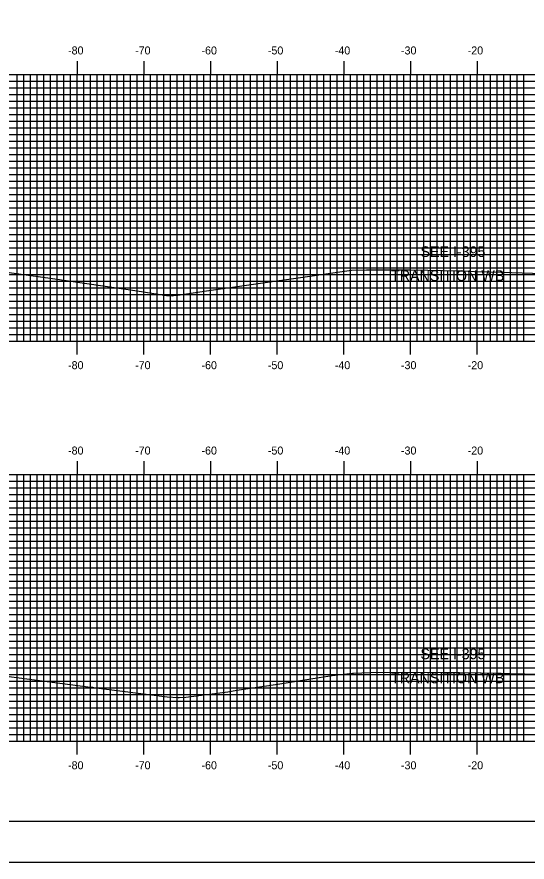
# Model space of a CAD drawing. Extents: x 854508 to 854851, y 364661 to 364881.
# Drawn here: x 854584.8 to 854661.3, y 364661.3 to 364788 of the extents above; entities that cross this region are included whole.
import ezdxf

# ---------------------------------------------------------------- set-up
doc = ezdxf.new("R2010")
doc.units = 0
for name, color, linetype in [('ANNOTATION', 7, 'Continuous'), ('BORDER', 7, 'Continuous'), ('H_V ANNOTATION', 7, 'Continuous'), ('M_Roadway_Centerline', 7, 'Continuous'), ('MAJOR', 7, 'Continuous'), ('MINOR', 7, 'Continuous'), ('PLOT BOUNDARY', 7, 'Continuous'), ('S_Roadway_Centerline', 7, 'Continuous')]:
    doc.layers.add(name, color=color, linetype=linetype)

msp = doc.modelspace()

# ---------------------------------------------------------------- linework, layer by layer
at = {"layer": 'BORDER'}
msp.add_lwpolyline([(854524.23, 364667.37), (854844.23, 364667.37), (854844.23, 364877.37), (854524.23, 364877.37)], close=True, dxfattribs=at)
at = {"layer": 'MAJOR'}
for p, q in [((854593.83, 364781.37), (854593.83, 364779.37)), ((854603.83, 364781.37), (854603.83, 364779.37)), ((854613.83, 364781.37), (854613.83, 364779.37)), ((854623.83, 364781.37), (854623.83, 364779.37)), ((854633.83, 364781.37), (854633.83, 364779.37)), ((854643.83, 364781.37), (854643.83, 364779.37)), ((854653.83, 364781.37), (854653.83, 364779.37)), ((854533.83, 364779.37), (854813.83, 364779.37)), ((854533.83, 364779.37), (854813.83, 364779.37)), ((854593.83, 364739.37), (854593.83, 364779.37)), ((854603.83, 364739.37), (854603.83, 364779.37)), ((854613.83, 364739.37), (854613.83, 364779.37)), ((854623.83, 364739.37), (854623.83, 364779.37)), ((854633.83, 364739.37), (854633.83, 364779.37)), ((854643.83, 364739.37), (854643.83, 364779.37)), ((854653.83, 364739.37), (854653.83, 364779.37)), ((854533.83, 364774.37), (854813.83, 364774.37)), ((854533.83, 364769.37), (854813.83, 364769.37)), ((854533.83, 364764.37), (854813.83, 364764.37)), ((854533.83, 364759.37), (854813.83, 364759.37)), ((854533.83, 364754.37), (854813.83, 364754.37)), ((854533.83, 364749.37), (854813.83, 364749.37)), ((854533.83, 364744.37), (854813.83, 364744.37)), ((854533.83, 364739.37), (854813.83, 364739.37)), ((854533.83, 364739.37), (854813.83, 364739.37)), ((854593.83, 364737.37), (854593.83, 364739.37)), ((854603.83, 364737.37), (854603.83, 364739.37)), ((854613.83, 364737.37), (854613.83, 364739.37)), ((854623.83, 364737.37), (854623.83, 364739.37)), ((854633.83, 364737.37), (854633.83, 364739.37)), ((854643.83, 364737.37), (854643.83, 364739.37)), ((854653.83, 364737.37), (854653.83, 364739.37)), ((854593.83, 364721.37), (854593.83, 364719.37)), ((854603.83, 364721.37), (854603.83, 364719.37)), ((854613.83, 364721.37), (854613.83, 364719.37)), ((854623.83, 364721.37), (854623.83, 364719.37)), ((854633.83, 364721.37), (854633.83, 364719.37)), ((854643.83, 364721.37), (854643.83, 364719.37)), ((854653.83, 364721.37), (854653.83, 364719.37)), ((854533.83, 364719.37), (854813.83, 364719.37)), ((854533.83, 364719.37), (854813.83, 364719.37)), ((854593.83, 364679.37), (854593.83, 364719.37)), ((854603.83, 364679.37), (854603.83, 364719.37)), ((854613.83, 364679.37), (854613.83, 364719.37)), ((854623.83, 364679.37), (854623.83, 364719.37)), ((854633.83, 364679.37), (854633.83, 364719.37)), ((854643.83, 364679.37), (854643.83, 364719.37)), ((854653.83, 364679.37), (854653.83, 364719.37)), ((854533.83, 364714.37), (854813.83, 364714.37)), ((854533.83, 364709.37), (854813.83, 364709.37)), ((854533.83, 364704.37), (854813.83, 364704.37)), ((854533.83, 364699.37), (854813.83, 364699.37)), ((854533.83, 364694.37), (854813.83, 364694.37)), ((854533.83, 364689.37), (854813.83, 364689.37)), ((854533.83, 364684.37), (854813.83, 364684.37)), ((854533.83, 364679.37), (854813.83, 364679.37)), ((854533.83, 364679.37), (854813.83, 364679.37)), ((854593.83, 364677.37), (854593.83, 364679.37)), ((854603.83, 364677.37), (854603.83, 364679.37)), ((854613.83, 364677.37), (854613.83, 364679.37)), ((854623.83, 364677.37), (854623.83, 364679.37)), ((854633.83, 364677.37), (854633.83, 364679.37)), ((854643.83, 364677.37), (854643.83, 364679.37)), ((854653.83, 364677.37), (854653.83, 364679.37))]:
    msp.add_line(p, q, dxfattribs=at)
at = {"layer": 'MINOR'}
for p, q in [((854533.83, 364778.37), (854813.83, 364778.37)), ((854584.83, 364739.37), (854584.83, 364779.37)), ((854585.83, 364739.37), (854585.83, 364779.37)), ((854586.83, 364739.37), (854586.83, 364779.37)), ((854587.83, 364739.37), (854587.83, 364779.37)), ((854588.83, 364739.37), (854588.83, 364779.37)), ((854589.83, 364739.37), (854589.83, 364779.37)), ((854590.83, 364739.37), (854590.83, 364779.37)), ((854591.83, 364739.37), (854591.83, 364779.37)), ((854592.83, 364739.37), (854592.83, 364779.37)), ((854594.83, 364739.37), (854594.83, 364779.37)), ((854595.83, 364739.37), (854595.83, 364779.37)), ((854596.83, 364739.37), (854596.83, 364779.37)), ((854597.83, 364739.37), (854597.83, 364779.37)), ((854598.83, 364739.37), (854598.83, 364779.37)), ((854599.83, 364739.37), (854599.83, 364779.37)), ((854600.83, 364739.37), (854600.83, 364779.37)), ((854601.83, 364739.37), (854601.83, 364779.37)), ((854602.83, 364739.37), (854602.83, 364779.37)), ((854604.83, 364739.37), (854604.83, 364779.37)), ((854605.83, 364739.37), (854605.83, 364779.37)), ((854606.83, 364739.37), (854606.83, 364779.37)), ((854607.83, 364739.37), (854607.83, 364779.37)), ((854608.83, 364739.37), (854608.83, 364779.37)), ((854609.83, 364739.37), (854609.83, 364779.37)), ((854610.83, 364739.37), (854610.83, 364779.37)), ((854611.83, 364739.37), (854611.83, 364779.37)), ((854612.83, 364739.37), (854612.83, 364779.37)), ((854614.83, 364739.37), (854614.83, 364779.37)), ((854615.83, 364739.37), (854615.83, 364779.37)), ((854616.83, 364739.37), (854616.83, 364779.37)), ((854617.83, 364739.37), (854617.83, 364779.37)), ((854618.83, 364739.37), (854618.83, 364779.37)), ((854619.83, 364739.37), (854619.83, 364779.37)), ((854620.83, 364739.37), (854620.83, 364779.37)), ((854621.83, 364739.37), (854621.83, 364779.37)), ((854622.83, 364739.37), (854622.83, 364779.37)), ((854624.83, 364739.37), (854624.83, 364779.37)), ((854625.83, 364739.37), (854625.83, 364779.37)), ((854626.83, 364739.37), (854626.83, 364779.37)), ((854627.83, 364739.37), (854627.83, 364779.37)), ((854628.83, 364739.37), (854628.83, 364779.37)), ((854629.83, 364739.37), (854629.83, 364779.37)), ((854630.83, 364739.37), (854630.83, 364779.37)), ((854631.83, 364739.37), (854631.83, 364779.37)), ((854632.83, 364739.37), (854632.83, 364779.37)), ((854634.83, 364739.37), (854634.83, 364779.37)), ((854635.83, 364739.37), (854635.83, 364779.37)), ((854636.83, 364739.37), (854636.83, 364779.37)), ((854637.83, 364739.37), (854637.83, 364779.37)), ((854638.83, 364739.37), (854638.83, 364779.37)), ((854639.83, 364739.37), (854639.83, 364779.37)), ((854640.83, 364739.37), (854640.83, 364779.37)), ((854641.83, 364739.37), (854641.83, 364779.37)), ((854642.83, 364739.37), (854642.83, 364779.37)), ((854644.83, 364739.37), (854644.83, 364779.37)), ((854645.83, 364739.37), (854645.83, 364779.37)), ((854646.83, 364739.37), (854646.83, 364779.37)), ((854647.83, 364739.37), (854647.83, 364779.37)), ((854648.83, 364739.37), (854648.83, 364779.37)), ((854649.83, 364739.37), (854649.83, 364779.37)), ((854650.83, 364739.37), (854650.83, 364779.37)), ((854651.83, 364739.37), (854651.83, 364779.37)), ((854652.83, 364739.37), (854652.83, 364779.37)), ((854654.83, 364739.37), (854654.83, 364779.37)), ((854655.83, 364739.37), (854655.83, 364779.37)), ((854656.83, 364739.37), (854656.83, 364779.37)), ((854657.83, 364739.37), (854657.83, 364779.37)), ((854658.83, 364739.37), (854658.83, 364779.37)), ((854659.83, 364739.37), (854659.83, 364779.37)), ((854660.83, 364739.37), (854660.83, 364779.37)), ((854533.83, 364777.37), (854813.83, 364777.37)), ((854533.83, 364776.37), (854813.83, 364776.37)), ((854533.83, 364775.37), (854813.83, 364775.37)), ((854533.83, 364773.37), (854813.83, 364773.37)), ((854533.83, 364772.37), (854813.83, 364772.37)), ((854533.83, 364771.37), (854813.83, 364771.37)), ((854533.83, 364770.37), (854813.83, 364770.37)), ((854533.83, 364768.37), (854813.83, 364768.37)), ((854533.83, 364767.37), (854813.83, 364767.37)), ((854533.83, 364766.37), (854813.83, 364766.37)), ((854533.83, 364765.37), (854813.83, 364765.37)), ((854533.83, 364763.37), (854813.83, 364763.37)), ((854533.83, 364762.37), (854813.83, 364762.37)), ((854533.83, 364761.37), (854813.83, 364761.37)), ((854533.83, 364760.37), (854813.83, 364760.37)), ((854533.83, 364758.37), (854813.83, 364758.37)), ((854533.83, 364757.37), (854813.83, 364757.37)), ((854533.83, 364756.37), (854813.83, 364756.37)), ((854533.83, 364755.37), (854813.83, 364755.37)), ((854533.83, 364753.37), (854813.83, 364753.37)), ((854533.83, 364752.37), (854813.83, 364752.37)), ((854533.83, 364751.37), (854813.83, 364751.37)), ((854533.83, 364750.37), (854813.83, 364750.37)), ((854533.83, 364748.37), (854813.83, 364748.37)), ((854533.83, 364747.37), (854813.83, 364747.37)), ((854533.83, 364746.37), (854813.83, 364746.37)), ((854533.83, 364745.37), (854813.83, 364745.37)), ((854533.83, 364743.37), (854813.83, 364743.37)), ((854533.83, 364742.37), (854813.83, 364742.37)), ((854533.83, 364741.37), (854813.83, 364741.37)), ((854533.83, 364740.37), (854813.83, 364740.37)), ((854584.83, 364679.37), (854584.83, 364719.37)), ((854585.83, 364679.37), (854585.83, 364719.37)), ((854586.83, 364679.37), (854586.83, 364719.37)), ((854587.83, 364679.37), (854587.83, 364719.37)), ((854588.83, 364679.37), (854588.83, 364719.37)), ((854589.83, 364679.37), (854589.83, 364719.37)), ((854590.83, 364679.37), (854590.83, 364719.37)), ((854591.83, 364679.37), (854591.83, 364719.37)), ((854592.83, 364679.37), (854592.83, 364719.37)), ((854594.83, 364679.37), (854594.83, 364719.37)), ((854595.83, 364679.37), (854595.83, 364719.37)), ((854596.83, 364679.37), (854596.83, 364719.37)), ((854597.83, 364679.37), (854597.83, 364719.37)), ((854598.83, 364679.37), (854598.83, 364719.37)), ((854599.83, 364679.37), (854599.83, 364719.37)), ((854600.83, 364679.37), (854600.83, 364719.37)), ((854601.83, 364679.37), (854601.83, 364719.37)), ((854602.83, 364679.37), (854602.83, 364719.37)), ((854604.83, 364679.37), (854604.83, 364719.37)), ((854605.83, 364679.37), (854605.83, 364719.37)), ((854606.83, 364679.37), (854606.83, 364719.37)), ((854607.83, 364679.37), (854607.83, 364719.37)), ((854608.83, 364679.37), (854608.83, 364719.37)), ((854609.83, 364679.37), (854609.83, 364719.37)), ((854610.83, 364679.37), (854610.83, 364719.37)), ((854611.83, 364679.37), (854611.83, 364719.37)), ((854612.83, 364679.37), (854612.83, 364719.37)), ((854614.83, 364679.37), (854614.83, 364719.37)), ((854615.83, 364679.37), (854615.83, 364719.37)), ((854616.83, 364679.37), (854616.83, 364719.37)), ((854617.83, 364679.37), (854617.83, 364719.37)), ((854618.83, 364679.37), (854618.83, 364719.37)), ((854619.83, 364679.37), (854619.83, 364719.37)), ((854620.83, 364679.37), (854620.83, 364719.37)), ((854621.83, 364679.37), (854621.83, 364719.37)), ((854622.83, 364679.37), (854622.83, 364719.37)), ((854624.83, 364679.37), (854624.83, 364719.37)), ((854625.83, 364679.37), (854625.83, 364719.37)), ((854626.83, 364679.37), (854626.83, 364719.37)), ((854627.83, 364679.37), (854627.83, 364719.37)), ((854628.83, 364679.37), (854628.83, 364719.37)), ((854629.83, 364679.37), (854629.83, 364719.37)), ((854630.83, 364679.37), (854630.83, 364719.37)), ((854631.83, 364679.37), (854631.83, 364719.37)), ((854632.83, 364679.37), (854632.83, 364719.37)), ((854634.83, 364679.37), (854634.83, 364719.37)), ((854635.83, 364679.37), (854635.83, 364719.37)), ((854636.83, 364679.37), (854636.83, 364719.37)), ((854637.83, 364679.37), (854637.83, 364719.37)), ((854638.83, 364679.37), (854638.83, 364719.37)), ((854639.83, 364679.37), (854639.83, 364719.37)), ((854640.83, 364679.37), (854640.83, 364719.37)), ((854641.83, 364679.37), (854641.83, 364719.37)), ((854642.83, 364679.37), (854642.83, 364719.37)), ((854644.83, 364679.37), (854644.83, 364719.37)), ((854645.83, 364679.37), (854645.83, 364719.37)), ((854646.83, 364679.37), (854646.83, 364719.37)), ((854647.83, 364679.37), (854647.83, 364719.37)), ((854648.83, 364679.37), (854648.83, 364719.37)), ((854649.83, 364679.37), (854649.83, 364719.37)), ((854650.83, 364679.37), (854650.83, 364719.37)), ((854651.83, 364679.37), (854651.83, 364719.37)), ((854652.83, 364679.37), (854652.83, 364719.37)), ((854654.83, 364679.37), (854654.83, 364719.37)), ((854655.83, 364679.37), (854655.83, 364719.37)), ((854656.83, 364679.37), (854656.83, 364719.37)), ((854657.83, 364679.37), (854657.83, 364719.37)), ((854658.83, 364679.37), (854658.83, 364719.37)), ((854659.83, 364679.37), (854659.83, 364719.37)), ((854660.83, 364679.37), (854660.83, 364719.37)), ((854533.83, 364718.37), (854813.83, 364718.37)), ((854533.83, 364717.37), (854813.83, 364717.37)), ((854533.83, 364716.37), (854813.83, 364716.37)), ((854533.83, 364715.37), (854813.83, 364715.37)), ((854533.83, 364713.37), (854813.83, 364713.37)), ((854533.83, 364712.37), (854813.83, 364712.37)), ((854533.83, 364711.37), (854813.83, 364711.37)), ((854533.83, 364710.37), (854813.83, 364710.37)), ((854533.83, 364708.37), (854813.83, 364708.37)), ((854533.83, 364707.37), (854813.83, 364707.37)), ((854533.83, 364706.37), (854813.83, 364706.37)), ((854533.83, 364705.37), (854813.83, 364705.37)), ((854533.83, 364703.37), (854813.83, 364703.37)), ((854533.83, 364702.37), (854813.83, 364702.37)), ((854533.83, 364701.37), (854813.83, 364701.37)), ((854533.83, 364700.37), (854813.83, 364700.37)), ((854533.83, 364698.37), (854813.83, 364698.37)), ((854533.83, 364697.37), (854813.83, 364697.37)), ((854533.83, 364696.37), (854813.83, 364696.37)), ((854533.83, 364695.37), (854813.83, 364695.37)), ((854533.83, 364693.37), (854813.83, 364693.37)), ((854533.83, 364692.37), (854813.83, 364692.37)), ((854533.83, 364691.37), (854813.83, 364691.37)), ((854533.83, 364690.37), (854813.83, 364690.37)), ((854533.83, 364688.37), (854813.83, 364688.37)), ((854533.83, 364687.37), (854813.83, 364687.37)), ((854533.83, 364686.37), (854813.83, 364686.37)), ((854533.83, 364685.37), (854813.83, 364685.37)), ((854533.83, 364683.37), (854813.83, 364683.37)), ((854533.83, 364682.37), (854813.83, 364682.37)), ((854533.83, 364681.37), (854813.83, 364681.37)), ((854533.83, 364680.37), (854813.83, 364680.37))]:
    msp.add_line(p, q, dxfattribs=at)
at = {"layer": 'PLOT BOUNDARY'}
msp.add_lwpolyline([(854508.05, 364661.25), (854848.05, 364661.25), (854848.05, 364881.25), (854508.05, 364881.25)], close=True, dxfattribs=at)
at = {"layer": 'S_Roadway_Centerline'}
for points in [[(854583.27, 364749.73), (854590.13, 364748.77), (854602.84, 364746.92), (854607.25, 364746.23), (854608.11, 364746.16), (854608.27, 364746.2), (854608.93, 364746.28), (854613.24, 364746.91), (854628.03, 364749.02), (854631.48, 364749.52), (854635.01, 364750), (854637.24, 364750.08), (854643.79, 364750.08), (854646.46, 364750.01), (854650.86, 364749.92), (854651.51, 364749.91), (854653.44, 364749.82), (854655.84, 364749.75), (854666.91, 364749.4)], [(854582.05, 364689.3), (854595.83, 364687.51), (854596.12, 364687.48), (854596.3, 364687.45), (854607.31, 364686.02), (854609, 364685.92), (854609.14, 364685.96), (854610.14, 364685.97), (854616.41, 364686.79), (854617.79, 364687.05), (854623.95, 364687.93), (854630.15, 364688.91), (854632.1, 364689.21), (854635.12, 364689.57), (854635.28, 364689.57), (854637.78, 364689.66), (854642.63, 364689.75), (854648.59, 364689.69), (854650.97, 364689.69), (854651.21, 364689.68), (854654.29, 364689.62), (854654.32, 364689.62), (854654.45, 364689.62), (854674.07, 364689.18)]]:
    msp.add_lwpolyline(points, dxfattribs=at)

# ---------------------------------------------------------------- texts
at = {"layer": 'ANNOTATION'}
for s, p in [('SEE I-395 ', (854645.33, 364752)), ('TRANSITION WB', (854640.92, 364748.4)), ('SEE I-395 ', (854645.33, 364691.68)), ('TRANSITION WB', (854640.92, 364688.08))]:
    msp.add_text(s, height=1.6, dxfattribs=at).set_placement(p)
at = {"layer": 'H_V ANNOTATION'}
for s, p in [('-80', (854592.46, 364782.37)), ('-70', (854602.52, 364782.37)), ('-60', (854612.48, 364782.37)), ('-50', (854622.44, 364782.37)), ('-40', (854632.48, 364782.37)), ('-30', (854642.41, 364782.37)), ('-20', (854652.42, 364782.37)), ('-80', (854592.46, 364735.17)), ('-70', (854602.52, 364735.17)), ('-60', (854612.48, 364735.17)), ('-50', (854622.44, 364735.17)), ('-40', (854632.48, 364735.17)), ('-30', (854642.41, 364735.17)), ('-20', (854652.42, 364735.17)), ('-80', (854592.46, 364722.37)), ('-70', (854602.52, 364722.37)), ('-60', (854612.48, 364722.37)), ('-50', (854622.44, 364722.37)), ('-40', (854632.48, 364722.37)), ('-30', (854642.41, 364722.37)), ('-20', (854652.42, 364722.37)), ('-80', (854592.46, 364675.17)), ('-70', (854602.52, 364675.17)), ('-60', (854612.48, 364675.17)), ('-50', (854622.44, 364675.17)), ('-40', (854632.48, 364675.17)), ('-30', (854642.41, 364675.17)), ('-20', (854652.42, 364675.17))]:
    msp.add_text(s, height=1.2, dxfattribs=at).set_placement(p)
at = {"layer": 'M_Roadway_Centerline'}
for s, p in [('C', (854651.51, 364749.91)), ('L', (854651.51, 364749.91)), ('C', (854651.2, 364689.68)), ('L', (854651.21, 364689.67))]:
    msp.add_text(s, height=0.0146, dxfattribs=at).set_placement(p)

doc.saveas('drawing.dxf')
